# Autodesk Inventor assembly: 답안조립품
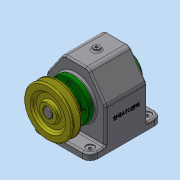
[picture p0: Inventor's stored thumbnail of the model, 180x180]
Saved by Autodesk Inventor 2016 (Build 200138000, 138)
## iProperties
Created: 2022-12
Part Number: 답안조립품
Material: 일반
Document SubType Name: Assembly
Designer: 하동건
Author: 하동건
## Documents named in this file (15)
- C:\Users\CAD06\Desktop\721206V1009\답안조립품.iam
- C:\Users\CAD06\Desktop\721206V1009\본체.ipt
- C:\Users\CAD06\Desktop\721206V1009\축.ipt
- C:\Users\CAD06\Desktop\721206V1009\오일 실 17 x 32 x 8.ipt
- C:\Users\CAD06\Desktop\721206V1009\뒤커버.ipt
- C:\Users\CAD06\Desktop\721206V1009\앞커버.ipt
- C:\Users\CAD06\Desktop\721206V1009\키 - 6 x 6 x 22.ipt
- C:\Users\CAD06\Desktop\721206V1009\스퍼기어.ipt
- C:\Users\CAD06\Desktop\721206V1009\칼라.ipt
- C:\Users\CAD06\Desktop\721206V1009\V-벨트풀리.ipt
- C:\Users\CAD06\Desktop\721206V1009\키 - 5 x 5 x 18.ipt
- C:\Users\CAD06\Desktop\721206V1009\멈춤나사 - M4x10.ipt
- C:\Users\CAD06\Desktop\721206V1009\볼트 M3 x 8.ipt
- C:\Users\CAD06\Desktop\721206V1009\볼트 M3 x 10.ipt
- C:\Users\CAD06\Desktop\721206V1009\베어링 6203.ipt
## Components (9 placed, 3 different names)
1. V-벨트풀리:1
2. ISO 4762 M3 x 10:1
3. ISO 4762 M3 x 10:2
4. ISO 4762 M3 x 10:3
5. ISO 4762 M3 x 10:4
6. ISO 4762 M3 x 8:1
7. ISO 4762 M3 x 8:2
8. ISO 4762 M3 x 8:3
9. ISO 4762 M3 x 8:4
